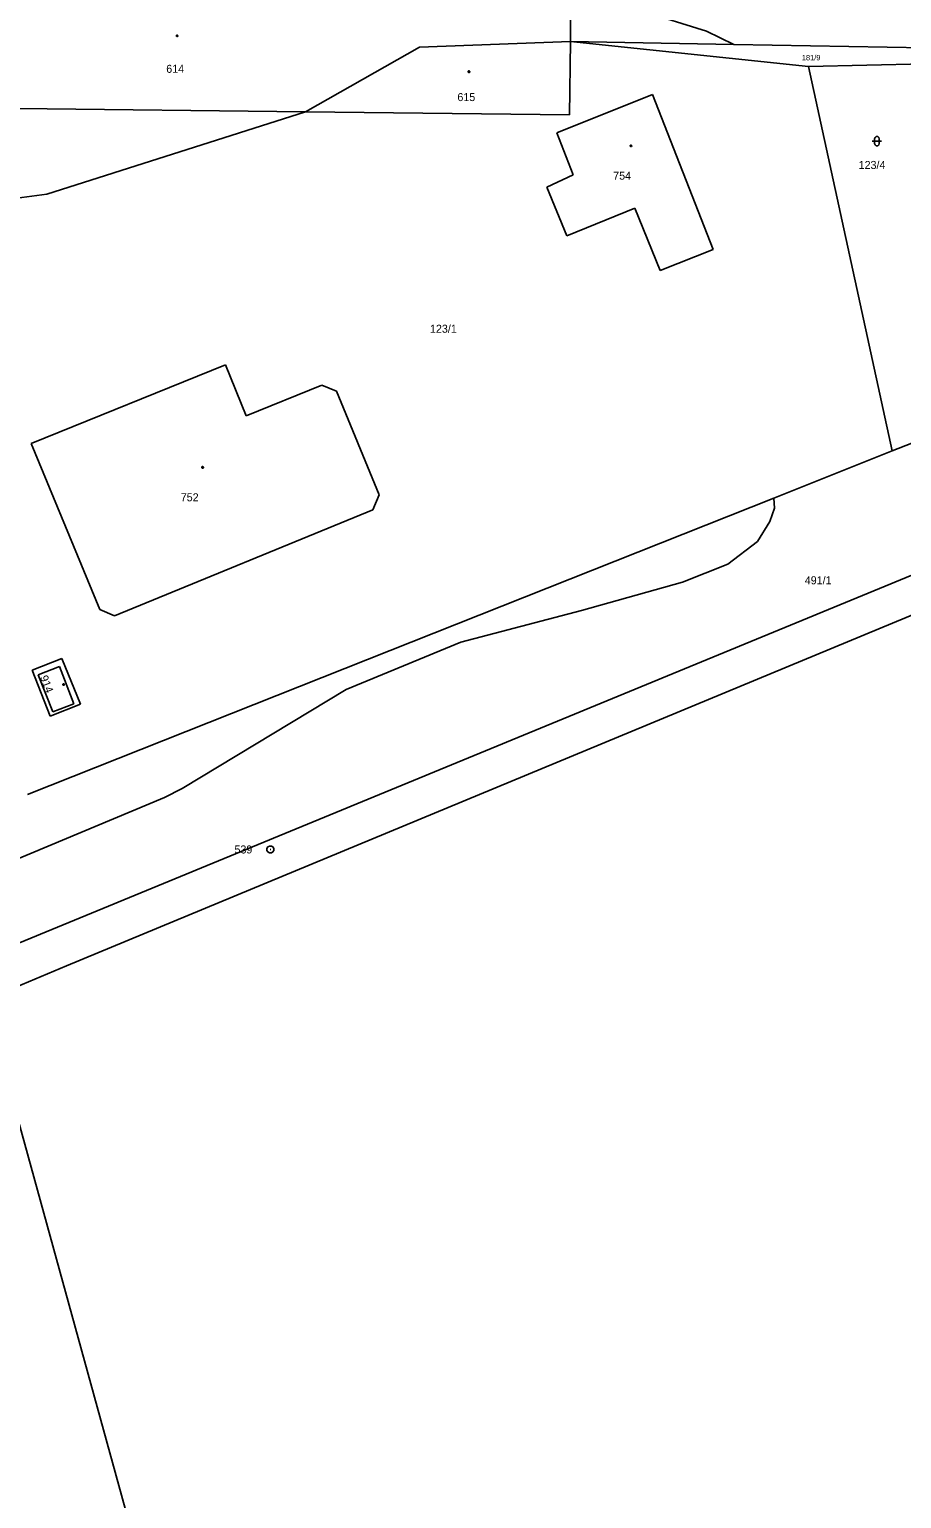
# Model space of a CAD drawing. Extents: x -757994 to -755874, y -1047691 to -1046119.
# Drawn here: x -756183.5 to -756090.9, y -1046741.5 to -1046585.4 of the extents above; entities that cross this region are included whole.
import ezdxf

# ---------------------------------------------------------------- set-up
doc = ezdxf.new("R2010")
doc.units = 0
doc.layers.add('katastrální mapa', color=7, linetype='Continuous')

msp = doc.modelspace()

# ---------------------------------------------------------------- linework, layer by layer
at = {"layer": 'katastrální mapa'}
for p, q in [((-756126.1, -1046586.7), (-756126.06, -1046582)), ((-756118.48, -1046583.49), (-756111.66, -1046585.6)), ((-756142.13, -1046587.31), (-756126.1, -1046586.7)), ((-756126.21, -1046594.5), (-756126.1, -1046586.7)), ((-756100.84, -1046589.35), (-756126.1, -1046586.7)), ((-756126.1, -1046586.7), (-756108.74, -1046587.02)), ((-756111.66, -1046585.6), (-756108.74, -1046587.02)), ((-756154.21, -1046594.17), (-756142.13, -1046587.31)), ((-756108.74, -1046587.02), (-756088.42, -1046587.39)), ((-756088.43, -1046589.09), (-756100.84, -1046589.35)), ((-756091.94, -1046630.21), (-756100.84, -1046589.35)), ((-756127.56, -1046596.41), (-756117.39, -1046592.34)), ((-756117.39, -1046592.34), (-756110.93, -1046608.8)), ((-756184.71, -1046593.82), (-756154.21, -1046594.17)), ((-756181.7, -1046602.92), (-756154.21, -1046594.17)), ((-756154.21, -1046594.17), (-756126.21, -1046594.5)), ((-756125.82, -1046600.88), (-756127.56, -1046596.41)), ((-755984.53, -1046599.97), (-756303.8, -1046731.6)), ((-756128.62, -1046602.18), (-756125.82, -1046600.88)), ((-756126.49, -1046607.35), (-756128.62, -1046602.18)), ((-756194.59, -1046604.68), (-756181.7, -1046602.92)), ((-756119.26, -1046604.42), (-756126.49, -1046607.35)), ((-756116.58, -1046611.02), (-756119.26, -1046604.42)), ((-756110.93, -1046608.8), (-756116.58, -1046611.02)), ((-756183.34, -1046629.41), (-756162.72, -1046621.06)), ((-756162.72, -1046621.06), (-756160.52, -1046626.47)), ((-756160.52, -1046626.47), (-756152.5, -1046623.2)), ((-756152.5, -1046623.2), (-756150.93, -1046623.87)), ((-756150.93, -1046623.87), (-756146.41, -1046634.85)), ((-756088.39, -1046628.82), (-756091.94, -1046630.21)), ((-756176.06, -1046647.05), (-756183.34, -1046629.41)), ((-756104.52, -1046635.21), (-756091.94, -1046630.21)), ((-756183.74, -1046666.69), (-756104.52, -1046635.21)), ((-756146.41, -1046634.85), (-756147.09, -1046636.45)), ((-756104.45, -1046636.3), (-756104.52, -1046635.21)), ((-756147.09, -1046636.45), (-756174.51, -1046647.72)), ((-756104.94, -1046637.71), (-756104.45, -1046636.3)), ((-756106.24, -1046639.81), (-756104.94, -1046637.71)), ((-756109.4, -1046642.22), (-756106.24, -1046639.81)), ((-756114.19, -1046644.14), (-756109.4, -1046642.22)), ((-756124.92, -1046647.14), (-756114.19, -1046644.14)), ((-756179.61, -1046684.89), (-756088.58, -1046647.12)), ((-756174.51, -1046647.72), (-756176.06, -1046647.05)), ((-756137.75, -1046650.5), (-756124.92, -1046647.14)), ((-756149.92, -1046655.55), (-756137.75, -1046650.5)), ((-756180.08, -1046652.24), (-756183.26, -1046653.5)), ((-756178.12, -1046657.12), (-756180.08, -1046652.24)), ((-756183.26, -1046653.5), (-756181.34, -1046658.39)), ((-756180.36, -1046653.1), (-756182.61, -1046653.97)), ((-756182.61, -1046653.97), (-756181.05, -1046657.93)), ((-756178.82, -1046657.05), (-756180.36, -1046653.1)), ((-756167.33, -1046666.06), (-756149.92, -1046655.55)), ((-756181.34, -1046658.39), (-756178.12, -1046657.12)), ((-756181.05, -1046657.93), (-756178.82, -1046657.05)), ((-756169.19, -1046667.01), (-756167.33, -1046666.06)), ((-756216.75, -1046686.91), (-756169.19, -1046667.01)), ((-756157.98, -1046672.53), (-756157.92, -1046672.53)), ((-756188.26, -1046688.52), (-756179.61, -1046684.89)), ((-756188.26, -1046688.52), (-756166.99, -1046765.66))]:
    msp.add_line(p, q, dxfattribs=at)
for points in [[(-756167.85, -1046586.02), (-756167.8, -1046586.03), (-756167.77, -1046586.08), (-756167.76, -1046586.11), (-756167.77, -1046586.16), (-756167.82, -1046586.19), (-756167.85, -1046586.2), (-756167.9, -1046586.18), (-756167.93, -1046586.15), (-756167.94, -1046586.11), (-756167.93, -1046586.07), (-756167.89, -1046586.03)], [(-756136.86, -1046589.84), (-756136.81, -1046589.85), (-756136.78, -1046589.89), (-756136.77, -1046589.92), (-756136.78, -1046589.97), (-756136.83, -1046590), (-756136.86, -1046590.01), (-756136.91, -1046589.99), (-756136.94, -1046589.96), (-756136.95, -1046589.92), (-756136.94, -1046589.88), (-756136.9, -1046589.84)], [(-756119.67, -1046597.72), (-756119.62, -1046597.73), (-756119.6, -1046597.77), (-756119.59, -1046597.8), (-756119.6, -1046597.85), (-756119.64, -1046597.88), (-756119.67, -1046597.89), (-756119.72, -1046597.87), (-756119.75, -1046597.84), (-756119.76, -1046597.8), (-756119.75, -1046597.76), (-756119.71, -1046597.72)], [(-756093.81, -1046597.05), (-756093.76, -1046596.91), (-756093.64, -1046596.82), (-756093.48, -1046596.82), (-756093.35, -1046596.91), (-756093.31, -1046597.05), (-756093.31, -1046597.55), (-756093.35, -1046597.7), (-756093.48, -1046597.79), (-756093.64, -1046597.79), (-756093.76, -1046597.7), (-756093.81, -1046597.55)], [(-756165.14, -1046631.87), (-756165.09, -1046631.88), (-756165.07, -1046631.92), (-756165.05, -1046631.95), (-756165.07, -1046631.99), (-756165.1, -1046632.03), (-756165.14, -1046632.03), (-756165.19, -1046632.02), (-756165.22, -1046631.99), (-756165.23, -1046631.95), (-756165.22, -1046631.91), (-756165.18, -1046631.87)], [(-756179.91, -1046654.94), (-756179.86, -1046654.95), (-756179.84, -1046654.99), (-756179.83, -1046655.02), (-756179.84, -1046655.07), (-756179.88, -1046655.1), (-756179.91, -1046655.11), (-756179.96, -1046655.09), (-756179.99, -1046655.06), (-756180, -1046655.02), (-756179.99, -1046654.98), (-756179.95, -1046654.94)], [(-756157.85, -1046672.17), (-756157.68, -1046672.27), (-756157.59, -1046672.44), (-756157.59, -1046672.63), (-756157.68, -1046672.8), (-756157.85, -1046672.9), (-756158.05, -1046672.9), (-756158.22, -1046672.8), (-756158.32, -1046672.63), (-756158.32, -1046672.44), (-756158.22, -1046672.27), (-756158.05, -1046672.17)]]:
    msp.add_lwpolyline(points, close=True, dxfattribs=at)
msp.add_lwpolyline([(-756094.06, -1046597.3), (-756093.43, -1046597.3), (-756093.06, -1046597.3)], dxfattribs=at)

# ---------------------------------------------------------------- texts
for s, height, p in [('181/9', 0.57, (-756101.53, -1046588.71)), ('614', 0.85, (-756169.01, -1046590.04)), ('615', 0.85, (-756138.1, -1046593.04)), ('123/4', 0.85, (-756095.5, -1046600.25)), ('754', 0.85, (-756121.56, -1046601.39)), ('123/1', 0.85, (-756141.01, -1046617.65)), ('752', 0.85, (-756167.47, -1046635.55)), ('491/1', 0.85, (-756101.22, -1046644.37)), ('539', 0.85, (-756161.77, -1046672.96))]:
    msp.add_text(s, height=height, dxfattribs=at).set_placement(p)
msp.add_text('914', height=0.85, rotation=291.0053, dxfattribs=at).set_placement((-756182.43, -1046654.23))

doc.saveas('drawing.dxf')
